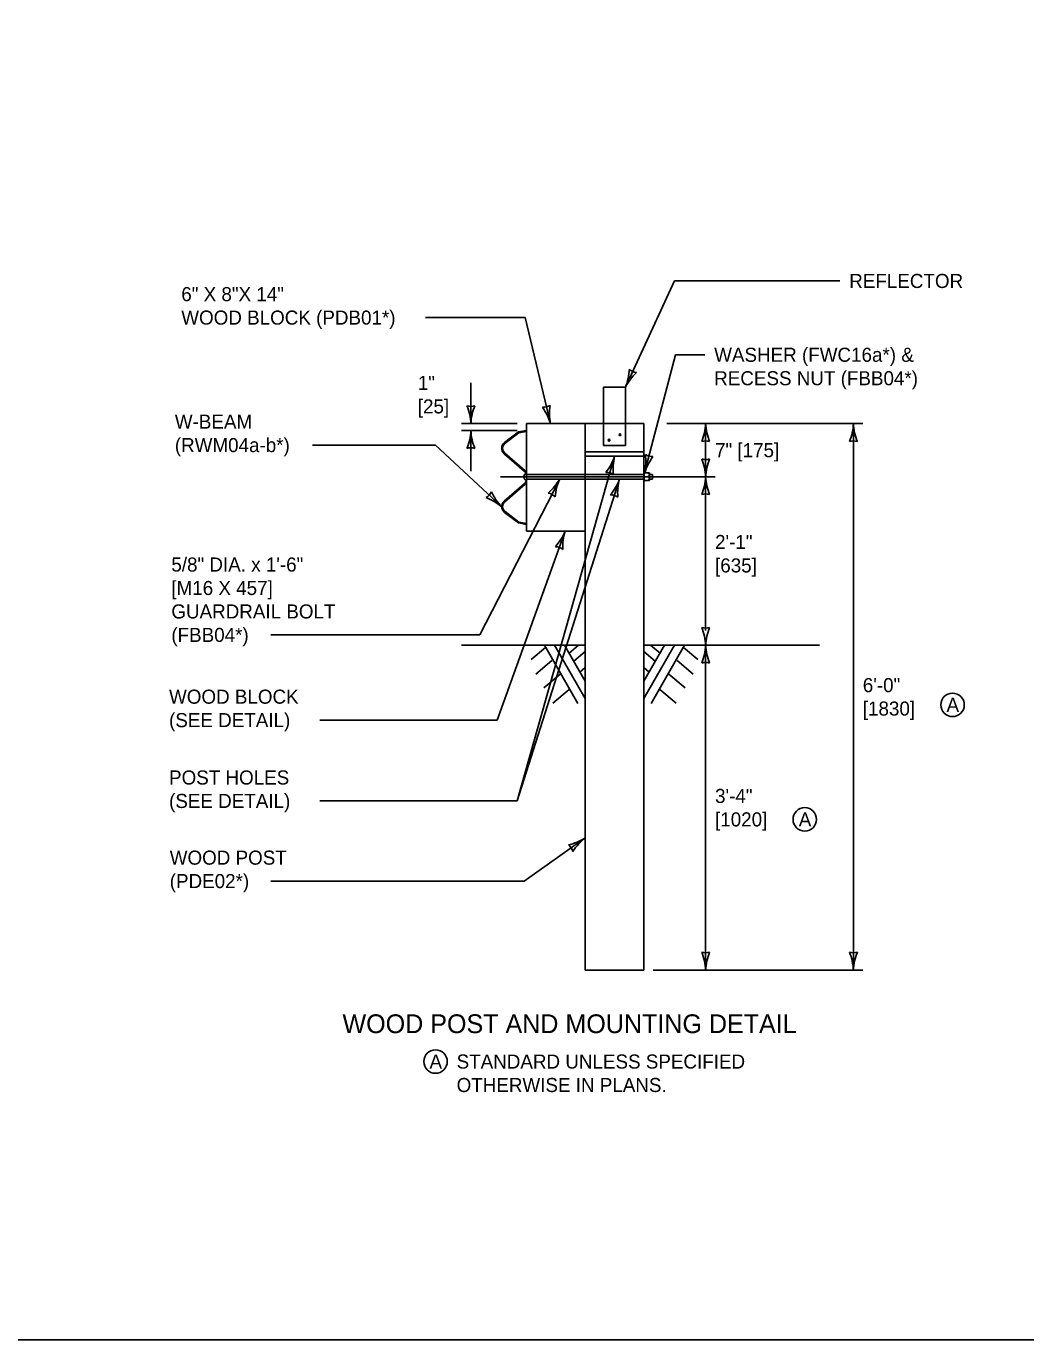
# Model space of a CAD drawing. Extents: x 49991.4 to 50021, y 49987.6 to 50011.4.
# Drawn here: x 50005.01 to 50009.28, y 49987.8 to 49993.4 of the extents above; entities that cross this region are included whole.
import ezdxf

# ---------------------------------------------------------------- set-up
doc = ezdxf.new("R2010")
doc.units = 0
for name, color, linetype in [('Level 1', 7, 'Continuous'), ('Level 2', 7, 'Continuous'), ('Level 3', 7, 'Continuous'), ('Level 4', 7, 'Continuous'), ('Level 5', 7, 'Continuous')]:
    doc.layers.add(name, color=color, linetype=linetype)

msp = doc.modelspace()

# ---------------------------------------------------------------- linework, layer by layer
at = {"layer": 'Level 1'}
for p, q in [((50007.1459, 49991.7047), (50007.4742, 49991.7047)), ((50007.1459, 49991.2457), (50007.1459, 49991.7047)), ((50007.396, 49990.7598), (50007.396, 49991.7047)), ((50007.4742, 49991.7047), (50007.4742, 49991.6109)), ((50007.5678, 49991.7047), (50007.6461, 49991.7047)), ((50007.5678, 49991.6109), (50007.5678, 49991.7047)), ((50007.6461, 49991.7047), (50007.6461, 49990.7598)), ((50007.1119, 49991.6691), (50007.0522, 49991.6244)), ((50007.1135, 49991.6655), (50007.0546, 49991.6213)), ((50007.1459, 49991.6752), (50007.1119, 49991.6691)), ((50007.1459, 49991.6711), (50007.1135, 49991.6655)), ((50007.4742, 49991.6109), (50007.5678, 49991.6109)), ((50007.0505, 49991.5766), (50007.1356, 49991.5025)), ((50007.0531, 49991.5795), (50007.1382, 49991.5054)), ((50007.144, 49991.4782), (50007.1343, 49991.4782)), ((50007.6461, 49991.4986), (50007.648, 49991.4986)), ((50007.648, 49991.4986), (50007.648, 49991.4575)), ((50007.648, 49991.4947), (50007.6696, 49991.4947)), ((50007.648, 49991.4782), (50007.6696, 49991.4782)), ((50007.6696, 49991.4617), (50007.6696, 49991.4947)), ((50007.6827, 49991.4878), (50007.6696, 49991.4878)), ((50007.6827, 49991.4878), (50007.6827, 49991.4684)), ((50007.0505, 49991.3742), (50007.1354, 49991.4481)), ((50007.0531, 49991.3713), (50007.1395, 49991.4466)), ((50007.6461, 49991.4575), (50007.648, 49991.4575)), ((50007.648, 49991.4617), (50007.6696, 49991.4617)), ((50007.6827, 49991.4684), (50007.6696, 49991.4684)), ((50007.1119, 49991.2812), (50007.0522, 49991.3264)), ((50007.1135, 49991.2849), (50007.0546, 49991.3295)), ((50007.1459, 49991.2752), (50007.1119, 49991.2812)), ((50007.1459, 49991.2792), (50007.1135, 49991.2849)), ((50007.1459, 49991.2457), (50007.396, 49991.2457)), ((50006.8684, 49990.7598), (50007.396, 49990.7598)), ((50007.2262, 49990.7503), (50007.1657, 49990.6995)), ((50007.3647, 49990.5122), (50007.222, 49990.7598)), ((50007.396, 49990.5324), (50007.2647, 49990.7598)), ((50007.396, 49990.6061), (50007.3074, 49990.7598)), ((50007.3672, 49990.7598), (50007.3269, 49990.7259)), ((50007.6461, 49990.6061), (50007.7347, 49990.7598)), ((50007.6461, 49990.7598), (50008.3961, 49990.7598)), ((50007.6461, 49990.5324), (50007.7773, 49990.7598)), ((50007.6749, 49990.7598), (50007.7152, 49990.7259)), ((50007.6774, 49990.5122), (50007.8201, 49990.7598)), ((50007.8159, 49990.7503), (50007.8763, 49990.6995)), ((50007.2541, 49990.6944), (50007.1855, 49990.6368)), ((50007.396, 49990.7328), (50007.3477, 49990.6922)), ((50007.6461, 49990.7328), (50007.6943, 49990.6922)), ((50007.7879, 49990.6944), (50007.8565, 49990.6368)), ((50007.2892, 49990.6362), (50007.2198, 49990.578)), ((50007.396, 49990.6646), (50007.3734, 49990.6455)), ((50007.6461, 49990.6646), (50007.6686, 49990.6455)), ((50007.7529, 49990.6362), (50007.8222, 49990.578)), ((50007.3276, 49990.5709), (50007.2582, 49990.5127)), ((50007.7145, 49990.5709), (50007.7838, 49990.5127))]:
    msp.add_line(p, q, dxfattribs=at)
for points in [[(49999.3835, 49998.9992), (50016.7501, 49998.9992), (50016.7501, 49987.7988), (49999.3835, 49987.7988)], [(50007.4742, 49991.8609), (50007.5678, 49991.8609), (50007.5678, 49991.7047), (50007.4742, 49991.7047)]]:
    msp.add_lwpolyline(points, close=True, dxfattribs=at)
for centre in [(50007.5444, 49991.6576), (50007.4976, 49991.6342)]:
    msp.add_circle(centre, 0.0039, dxfattribs=at)
for centre, radius, start, end in [((50007.0707, 49991.5998), 0.0308, 126.8969, 228.9393), ((50007.0707, 49991.5998), 0.0269, 126.8969, 228.9393), ((50007.1155, 49991.4794), 0.0306, 5.9023, 48.9393), ((50007.1155, 49991.4794), 0.0345, 28.1043, 48.9393), ((50007.1155, 49991.4714), 0.0306, 310.4718, 354.0977), ((50007.1155, 49991.4714), 0.0345, 314.1015, 331.8957), ((50007.0707, 49991.351), 0.0308, 131.0607, 233.1031), ((50007.0707, 49991.351), 0.0269, 131.0607, 233.1031)]:
    msp.add_arc(centre, radius, start, end, dxfattribs=at)
for centre, major_axis, ratio, start_param, end_param in [((50007.144, 49991.478), (0, 0.0146), 0.663267, 0.091019, 3.253139), ((50007.6612, 49991.4865), (0.00829, 0.00104), 0.990733, 4.594607, 7.611796), ((50007.6612, 49991.47), (-0.00829, -0.00104), 0.990733, 1.560784, 4.582629)]:
    msp.add_ellipse(centre, major_axis=major_axis, ratio=ratio, start_param=start_param, end_param=end_param, dxfattribs=at)
at = {"layer": 'Level 2'}
for centre in [(50008.9629, 49990.5057), (50008.3326, 49990.0174), (50006.7575, 49988.9849)]:
    msp.add_circle(centre, 0.05, dxfattribs=at)
at = {"layer": 'Level 3'}
for p, q in [((50007.7768, 49992.3131), (50007.5678, 49991.8609)), ((50008.4822, 49992.3131), (50007.7768, 49992.3131)), ((50006.7146, 49992.1569), (50007.1403, 49992.1569)), ((50007.1403, 49992.1569), (50007.2474, 49991.7047)), ((50007.6496, 49991.4947), (50007.7814, 49991.9984)), ((50007.7814, 49991.9984), (50007.9062, 49991.9984)), ((50006.9084, 49991.8782), (50006.9084, 49991.7047)), ((50006.8684, 49991.7047), (50007.1059, 49991.7047)), ((50007.7446, 49991.7047), (50008.5801, 49991.7047)), ((50007.9098, 49991.4782), (50007.9098, 49991.7047)), ((50008.5401, 49989.375), (50008.5401, 49991.7047)), ((50006.8684, 49991.6752), (50007.1059, 49991.6752)), ((50006.9084, 49991.6752), (50006.9084, 49991.5018)), ((50006.2331, 49991.6133), (50006.7571, 49991.6133)), ((50006.7571, 49991.6133), (50007.04, 49991.3499)), ((50007.1051, 49990.096), (50007.5211, 49991.5655)), ((50007.9098, 49990.8222), (50007.9098, 49991.4782)), ((50006.9462, 49990.804), (50007.2874, 49991.4684)), ((50007.1051, 49990.096), (50007.5423, 49991.4684)), ((50007.0198, 49990.4406), (50007.3104, 49991.2457)), ((50006.0546, 49990.804), (50006.9462, 49990.804)), ((50007.9098, 49989.375), (50007.9098, 49990.7598)), ((50007.0198, 49990.4406), (50006.2646, 49990.4406)), ((50006.2646, 49990.096), (50007.1051, 49990.096)), ((50007.1356, 49989.7543), (50007.396, 49989.9388)), ((50006.0546, 49989.7543), (50007.1356, 49989.7543)), ((50007.6861, 49989.375), (50008.5801, 49989.375))]:
    msp.add_line(p, q, dxfattribs=at)
for centre, radius, start, end in [((50007.3517, 49991.9481), 0.233, 338.0186, 357.2685), ((50007.7656, 49991.7594), 0.2223, 132.6473, 152.8309), ((50007.6216, 49991.9773), 0.0548, 227.3302, 263.0525), ((50006.9084, 49991.8329), 0.0548, 252.1388, 287.8612), ((50006.6756, 49991.6932), 0.233, 2.8273, 22.0772), ((50007.1305, 49991.6956), 0.2223, 157.456, 177.6395), ((50007.2179, 49991.8294), 0.0548, 265.4637, 301.1861), ((50007.0236, 49991.6399), 0.233, 16.1522, 35.402), ((50007.4657, 49991.747), 0.2223, 170.7809, 190.9644), ((50007.6877, 49991.7139), 0.2223, 337.456, 357.6395), ((50008.1425, 49991.7162), 0.233, 182.8273, 202.0772), ((50008.318, 49991.7139), 0.2223, 337.456, 357.6395), ((50008.7728, 49991.7162), 0.233, 182.8273, 202.0772), ((50006.6756, 49991.6867), 0.233, 337.9228, 357.1727), ((50007.1305, 49991.6843), 0.2223, 182.3605, 202.544), ((50006.9084, 49991.547), 0.0548, 72.1388, 107.8612), ((50007.9098, 49991.5765), 0.0548, 72.1388, 107.8612), ((50008.5401, 49991.5765), 0.0548, 72.1388, 107.8612), ((50007.3002, 49991.6395), 0.233, 322.2246, 341.4745), ((50007.7374, 49991.5142), 0.2223, 166.6623, 186.8458), ((50007.4216, 49991.5425), 0.233, 348.1611, 7.4109), ((50007.8622, 49991.4296), 0.2223, 142.7898, 162.9733), ((50007.6821, 49991.6188), 0.0548, 237.4726, 273.1949), ((50007.9098, 49991.6065), 0.0548, 252.1388, 287.8612), ((50007.6771, 49991.4668), 0.233, 2.8273, 22.0772), ((50008.132, 49991.4691), 0.2223, 157.456, 177.6395), ((50007.4864, 49991.4421), 0.0548, 56.4406, 92.163), ((50007.6877, 49991.4874), 0.2223, 337.456, 357.6395), ((50008.1425, 49991.4897), 0.233, 182.8273, 202.0772), ((50007.0857, 49991.585), 0.233, 310.7387, 329.9885), ((50007.4892, 49991.3751), 0.2223, 155.1763, 175.3598), ((50007.3336, 49991.545), 0.2223, 319.6723, 339.8558), ((50007.7674, 49991.4083), 0.233, 165.0436, 184.2935), ((50006.9461, 49991.4373), 0.0548, 299.1807, 334.9031), ((50006.8953, 49991.1811), 0.2223, 49.4024, 69.5859), ((50007.207, 49991.5124), 0.233, 204.9647, 224.2146), ((50007.2289, 49991.3544), 0.0548, 44.9547, 80.677), ((50007.5032, 49991.3464), 0.0548, 54.3551, 90.0775), ((50007.9098, 49991.35), 0.0548, 72.1388, 107.8612), ((50007.0954, 49991.3356), 0.233, 318.0731, 337.323), ((50007.5225, 49991.1789), 0.2223, 162.5108, 182.6943), ((50007.2669, 49991.1251), 0.0548, 52.2891, 88.0115), ((50007.9098, 49990.8881), 0.0548, 252.1388, 287.8612), ((50007.6771, 49990.7484), 0.233, 2.8273, 22.0772), ((50008.132, 49990.7507), 0.2223, 157.456, 177.6395), ((50007.6877, 49990.769), 0.2223, 337.456, 357.6395), ((50008.1425, 49990.7713), 0.233, 182.8273, 202.0772), ((50007.9098, 49990.6316), 0.0548, 72.1388, 107.8612), ((50007.2751, 49990.1254), 0.2223, 282.7682, 302.9517), ((50007.2914, 49989.8647), 0.0548, 17.451, 53.1734), ((50007.5399, 49989.7556), 0.233, 128.1395, 147.3894), ((50007.9098, 49989.5033), 0.0548, 252.1388, 287.8612), ((50007.6771, 49989.3636), 0.233, 2.8273, 22.0772), ((50008.132, 49989.3659), 0.2223, 157.456, 177.6395), ((50008.5401, 49989.5033), 0.0548, 252.1388, 287.8612), ((50008.3074, 49989.3636), 0.233, 2.8273, 22.0772), ((50008.7623, 49989.3659), 0.2223, 157.456, 177.6395)]:
    msp.add_arc(centre, radius, start, end, dxfattribs=at)
at = {"layer": 'Level 4'}
for p, q in [((50007.6461, 49991.5849), (50007.396, 49991.5849)), ((50007.6461, 49991.5655), (50007.396, 49991.5655)), ((50007.6461, 49991.4878), (50007.1459, 49991.4878)), ((50007.6461, 49991.4684), (50007.1459, 49991.4684)), ((50007.396, 49990.7598), (50007.396, 49989.375)), ((50007.6461, 49989.375), (50007.6461, 49990.7598)), ((50007.396, 49989.375), (50007.6461, 49989.375))]:
    msp.add_line(p, q, dxfattribs=at)
at = {"layer": 'Level 5'}
msp.add_line((50007.0342, 49991.4782), (50007.9498, 49991.4782), dxfattribs=at)

# ---------------------------------------------------------------- texts
at = {"layer": 'Level 2'}
for s, height, p in [('REFLECTOR', 0.06, (50008.5222, 49992.2831)), ('6" X 8"X 14"', 0.06, (50005.673, 49992.2269)), ('WOOD BLOCK (PDB01*)', 0.06, (50005.673, 49992.1269)), ('WASHER (FWC16a*) &', 0.06, (50007.9462, 49991.9684)), ('RECESS NUT (FBB04*)', 0.06, (50007.9462, 49991.8684)), ('1"', 0.06, (50006.6818, 49991.8482)), ('[25]', 0.06, (50006.6818, 49991.7482)), ('W-BEAM', 0.06, (50005.6455, 49991.6833)), ('(RWM04a-b*)', 0.06, (50005.6455, 49991.5833)), ('7" [175]', 0.06, (50007.9498, 49991.5615)), ('2\'-1"', 0.06, (50007.9498, 49991.1702)), ('5/8" DIA. x 1\'-6"', 0.06, (50005.6306, 49991.074)), ('[635]', 0.06, (50007.9498, 49991.0702)), ('[M16 X 457]', 0.06, (50005.6306, 49990.974)), ('GUARDRAIL BOLT', 0.06, (50005.6306, 49990.874)), ('(FBB04*)', 0.06, (50005.6306, 49990.774)), ('6\'-0" ', 0.06, (50008.5801, 49990.5599)), ('WOOD BLOCK', 0.06, (50005.6208, 49990.5106)), ('[1830]', 0.06, (50008.5801, 49990.4599)), ('A', 0.06, (50008.9372, 49990.4757)), ('(SEE DETAIL)', 0.06, (50005.6208, 49990.4106)), ('POST HOLES', 0.06, (50005.6208, 49990.166)), ('3\'-4" ', 0.06, (50007.9498, 49990.0874)), ('(SEE DETAIL)', 0.06, (50005.6208, 49990.066)), ('[1020]', 0.06, (50007.9498, 49989.9874)), ('A', 0.06, (50008.3069, 49989.9874)), ('WOOD POST', 0.06, (50005.6237, 49989.8243)), ('(PDE02*)', 0.06, (50005.6237, 49989.7243)), ('WOOD POST AND MOUNTING DETAIL', 0.08, (50006.3606, 49989.1061)), ('A', 0.06, (50006.7318, 49988.9549)), ('STANDARD UNLESS SPECIFIED', 0.06, (50006.8475, 49988.9549)), ('OTHERWISE IN PLANS.', 0.06, (50006.8475, 49988.8549))]:
    msp.add_text(s, height=height, dxfattribs=at).set_placement(p)

doc.saveas('drawing.dxf')
